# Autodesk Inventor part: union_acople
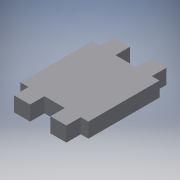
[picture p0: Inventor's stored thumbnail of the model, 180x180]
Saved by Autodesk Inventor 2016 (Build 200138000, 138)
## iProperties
Created: 2017-06
Part Number: union_acople
Material: Generic
Document SubType Name: Modeling
Designer: laboratorioesan
Density: 1 g/cm^3
Appearance: Default
Author: laboratorioesan
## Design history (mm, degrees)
sketch "Sketch1"
  geometry: L1 (0, 0)-(-20, 0) reference; L2 (0, 0)-(0, 18.5) reference; L3 (-20, 18.5)-(0, 18.5) reference; L4 (-20, 0)-(-20, 18.5) reference; L5 (45.466, 0)-(25.466, 0) reference; L6 (45.466, 0)-(45.466, 18.5) reference; L7 (25.466, 18.5)-(45.466, 18.5) reference; L8 (25.466, 0)-(25.466, 18.5) reference; L9 (-50, 128)-(34.685, 128) reference; L10 (34.685, 128)-(178.3, 128) reference; L11 (-42.5, 0)-(-42.5, 18.5) reference; L12 (55, 0)-(55, 18.5) reference; L13 (-30, 0)-(-30, 18.5) reference; L14 (-30, 18.5)-(55, 18.5); L15 (55, 18.5)-(55, 107.5); L16 (55, 107.5)-(-30, 107.5); L17 (-30, 107.5)-(-30, 18.5); L18 (-20, 18.5)-(0, 18.5); L19 (0, 18.5)-(0, 0.5); L20 (0, 0.5)-(-20, 0.5); L21 (-20, 0.5)-(-20, 18.5); L22 (25.466, 18.5)-(45.466, 18.5); L23 (45.466, 18.5)-(45.466, 0.5); L24 (45.466, 0.5)-(25.466, 0.5); L25 (25.466, 0.5)-(25.466, 18.5); L26 (-20, 107.5)-(0, 107.5); L27 (0, 107.5)-(0, 125.5); L28 (0, 125.5)-(-20, 125.5); L29 (-20, 125.5)-(-20, 107.5); L30 (25.466, 107.5)-(45.466, 107.5); L31 (45.466, 107.5)-(45.466, 125.5); L32 (45.466, 125.5)-(25.466, 125.5); L33 (25.466, 125.5)-(25.466, 107.5)
  constraints: 42 end point, 10 parallel, 5 horizontal, 5 perpendicular, 5 point on line, 1 vertical, 1 vertical alignment, 2 other
  dimensions: "d1" = 18 distance of L18.end L19.end; "d2" = 18 distance of L22.end L23.end; "d3" = 89 distance of L14.end L15.end; "d4" = 18 distance of L27.end L26.end
extrude "Extrusion1" new body sketch "Sketch1" distance "d5" = 18.5; taper "d6" = 0 deg
body "Solid1"
node "Reference1"
node "Reference2"
node "Reference3"
node "Reference4"
node "Reference5"
node "Reference6"
